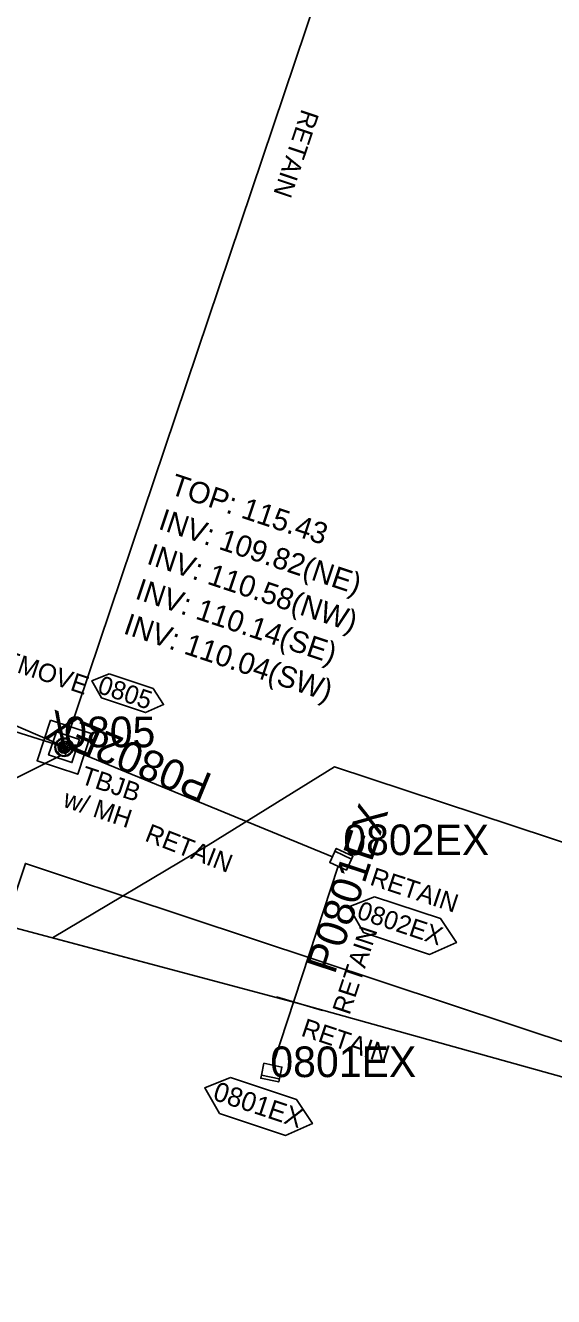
# Model space of a CAD drawing. Extents: x 2296558 to 2299313, y 599200 to 601383.
# Drawn here: x 2299102.6 to 2299188.8, y 599410.6 to 599618.1 of the extents above; entities that cross this region are included whole.
import ezdxf

# ---------------------------------------------------------------- set-up
doc = ezdxf.new("R2010")
doc.units = 0
for name, color, linetype in [('Exist Drainage Structure Catch Basin CELL', 7, 'Continuous'), ('Prop Drainage Structure Box Number Symbol CELL', 7, 'Continuous'), ('Prop Drainage Structure Catch Basin Grate 840 03F Label', 7, 'Continuous'), ('Prop Drainage Structure Catch Basin Grate 840 03G Label', 7, 'Continuous'), ('Prop Drainage Structure Junction Box with Manhole TB CELL', 7, 'Continuous'), ('Prop Drainage Structure Pipe RCP 18in Class IV', 7, 'Continuous'), ('Prop Drainage Structure Pipe Removal', 7, 'Continuous'), ('Prop Drainage Structure Plot Symbol 20 Scale', 7, 'Continuous'), ('Prop Drainage Structure Plot Symbol 50 Scale', 7, 'Continuous'), ('Prop Drainage Structure Retain Label', 7, 'Continuous'), ('Prop Drainage Structure Tops and Inverts LABEL', 7, 'Continuous'), ('Prop Plan Preparation Watershed Post Construction', 7, 'Continuous'), ('Scratch_Level_1', 7, 'Continuous'), ('Scratch_Level_3', 7, 'Continuous'), ('Scratch_Level_5', 7, 'Continuous'), ('Scratch_Level_9', 7, 'Continuous')]:
    doc.layers.add(name, color=color, linetype=linetype)

msp = doc.modelspace()

# ---------------------------------------------------------------- linework, layer by layer
at = {"layer": 'Exist Drainage Structure Catch Basin CELL'}
for p, q in [((2299152.69, 599482.4), (2299152.69, 599482.4)), ((2299154.68, 599483.12), (2299154.68, 599483.12)), ((2299153.63, 599480.86), (2299153.63, 599480.86)), ((2299154.05, 599481.76), (2299154.05, 599481.76)), ((2299155.41, 599481.13), (2299155.41, 599481.13)), ((2299141.31, 599447.72), (2299141.31, 599447.72)), ((2299142.77, 599447.41), (2299142.77, 599447.41)), ((2299142.98, 599448.39), (2299142.98, 599448.39)), ((2299144.24, 599447.1), (2299144.24, 599447.1)), ((2299142.46, 599445.94), (2299142.46, 599445.94))]:
    msp.add_line(p, q, dxfattribs=at)
for points in [[(2299153.11, 599483.3), (2299155.83, 599482.03), (2299156.04, 599482.49), (2299153.32, 599483.76), (2299152.27, 599481.49), (2299154.99, 599480.22), (2299155.83, 599482.03)], [(2299144.03, 599446.12), (2299141.1, 599446.74), (2299141, 599446.25), (2299143.93, 599445.63), (2299144.45, 599448.07), (2299141.51, 599448.7), (2299141.1, 599446.74)]]:
    msp.add_lwpolyline(points, dxfattribs=at)
at = {"layer": 'Prop Drainage Structure Box Number Symbol CELL'}
for points in [[(2299116.25, 599512.25), (2299123.43, 599509.87), (2299125.15, 599507.25), (2299122.23, 599505.96), (2299115.05, 599508.34), (2299113.45, 599511.14), (2299116.25, 599512.25)], [(2299159.58, 599475.89), (2299170.34, 599472.31), (2299172.93, 599468.39), (2299168.55, 599466.45), (2299157.78, 599470.02), (2299155.38, 599474.21), (2299159.58, 599475.89)], [(2299136.08, 599446.35), (2299146.85, 599442.78), (2299149.43, 599438.85), (2299145.05, 599436.91), (2299134.28, 599440.49), (2299131.88, 599444.68), (2299136.08, 599446.35)]]:
    msp.add_lwpolyline(points, dxfattribs=at)
at = {"layer": 'Prop Drainage Structure Junction Box with Manhole TB CELL'}
for p, q in [((2299109.37, 599501.61), (2299109.37, 599501.61)), ((2299107.62, 599500.73), (2299107.62, 599500.73)), ((2299108.49, 599498.98), (2299108.49, 599498.98)), ((2299108.93, 599500.29), (2299108.93, 599500.29)), ((2299110.25, 599499.86), (2299110.25, 599499.86))]:
    msp.add_line(p, q, dxfattribs=at)
for points in [[(2299108.63, 599501.65), (2299108.71, 599501.26), (2299108.75, 599501.27), (2299108.67, 599501.65)], [(2299108.63, 599501.65), (2299108.71, 599501.26), (2299108.75, 599501.27), (2299108.67, 599501.65)], [(2299109.95, 599501.23), (2299109.66, 599500.97), (2299109.68, 599500.94), (2299109.98, 599501.2)], [(2299109.95, 599501.23), (2299109.66, 599500.97), (2299109.68, 599500.94), (2299109.98, 599501.2)], [(2299107.62, 599500.75), (2299108, 599500.63), (2299107.98, 599500.59), (2299107.61, 599500.71)], [(2299107.61, 599500.71), (2299107.98, 599500.59), (2299108, 599500.63), (2299107.62, 599500.75)], [(2299107.91, 599499.36), (2299108.2, 599499.62), (2299108.18, 599499.65), (2299107.88, 599499.39)], [(2299107.91, 599499.36), (2299108.2, 599499.62), (2299108.18, 599499.65), (2299107.88, 599499.39)], [(2299109.23, 599498.94), (2299109.15, 599499.33), (2299109.11, 599499.32), (2299109.19, 599498.93)], [(2299109.23, 599498.94), (2299109.15, 599499.33), (2299109.11, 599499.32), (2299109.19, 599498.93)], [(2299110.25, 599499.88), (2299109.88, 599500), (2299109.86, 599499.96), (2299110.24, 599499.84)], [(2299110.25, 599499.88), (2299109.88, 599500), (2299109.86, 599499.96), (2299110.24, 599499.84)]]:
    msp.add_lwpolyline(points, dxfattribs=at)
for radius in [1.39, 0.99, 0.953, 0.87, 0.625, 0.583, 0.333, 0.292, 0.0834, 0.0416]:
    msp.add_circle((2299108.93, 599500.29), radius, dxfattribs=at)
msp.add_arc((2299108.93, 599500.29), 0.0834, 71.6371, 71.6371, dxfattribs=at)
at = {"layer": 'Prop Drainage Structure Pipe RCP 18in Class IV'}
msp.add_line((2299045.49, 599520.29), (2299107.62, 599500.73), dxfattribs=at)
at = {"layer": 'Prop Drainage Structure Pipe Removal'}
msp.add_line((2299068.84, 599517.73), (2299108.93, 599500.4), dxfattribs=at)
at = {"layer": 'Prop Drainage Structure Plot Symbol 20 Scale'}
msp.add_lwpolyline([(2299107.66, 599502.82), (2299111.46, 599501.56), (2299110.2, 599497.77), (2299106.4, 599499.03)], close=True, dxfattribs=at)
msp.add_circle((2299108.93, 599500.29), 1.5, dxfattribs=at)
at = {"layer": 'Prop Drainage Structure Plot Symbol 50 Scale'}
msp.add_lwpolyline([(2299106.71, 599504.72), (2299113.35, 599502.51), (2299111.15, 599495.87), (2299104.51, 599498.07)], close=True, dxfattribs=at)
msp.add_circle((2299108.93, 599500.29), 1.5, dxfattribs=at)
at = {"layer": 'Prop Plan Preparation Watershed Post Construction'}
msp.add_lwpolyline([(2299299.35, 599416.01), (2299307.79, 599446.97), (2299301.84, 599447.48), (2299293.51, 599450.64), (2299153.01, 599497.07), (2299132.4, 599484.31), (2299107.04, 599469.18), (2299147.02, 599458.5), (2299299.35, 599416.01)], dxfattribs=at)
msp.add_lwpolyline([(2299034.3, 599277.17), (2299068.89, 599265.54), (2299164.35, 599258.21), (2299187.08, 599250.1), (2299278.03, 599200.45), (2299283.1, 599276.07), (2299285.25, 599366.73), (2299299.35, 599416.01), (2299147.02, 599458.5), (2299099.24, 599471.26)], close=True, dxfattribs=at)
at = {"layer": 'Scratch_Level_1'}
msp.add_line((2299143.55, 599459.51), (2299151.1, 599457.31), dxfattribs=at)
msp.add_lwpolyline([(2299299.35, 599416.01), (2299118.35, 599476.09), (2299109.81, 599478.93), (2299102.61, 599481.32), (2299034.3, 599277.17)], dxfattribs=at)
at = {"layer": 'Scratch_Level_9'}
for p, q in [((2299109.37, 599501.61), (2299188.64, 599737.25)), ((2299055.32, 599472.12), (2299108.49, 599498.98)), ((2299152.69, 599482.4), (2299110.25, 599499.86)), ((2299142.98, 599448.39), (2299153.63, 599480.86))]:
    msp.add_line(p, q, dxfattribs=at)

# ---------------------------------------------------------------- texts
at = {"layer": 'Prop Drainage Structure Box Number Symbol CELL'}
for s, height, p in [('0805', 3, (2299114.19, 599509.21)), ('0802EX', 3, (2299156.51, 599472.39)), ('0801EX', 3.15, (2299133.02, 599442.78))]:
    msp.add_text(s, height=height, rotation=341.6372, dxfattribs=at).set_placement(p)
at = {"layer": 'Prop Drainage Structure Catch Basin Grate 840 03F Label'}
for s, p in [('TBJB', (2299111.46, 599494.42)), (' w/ MH', (2299107.51, 599490.99))]:
    msp.add_text(s, height=3, rotation=341.6372, dxfattribs=at).set_placement(p)
at = {"layer": 'Prop Drainage Structure Catch Basin Grate 840 03G Label'}
msp.add_text('REMOVE', height=3, rotation=341.6372, dxfattribs=at).set_placement((2299095.8, 599514.3))
at = {"layer": 'Prop Drainage Structure Retain Label'}
for rotation, p in [(251.38, (2299147.72, 599604.62)), (338.7633, (2299121.93, 599485.07)), (341.6372, (2299158.64, 599477.88)), (71.6794, (2299155.47, 599456.45)), (341.6372, (2299147.43, 599453.22))]:
    msp.add_text('RETAIN', height=3, rotation=rotation, dxfattribs=at).set_placement(p)
at = {"layer": 'Prop Drainage Structure Tops and Inverts LABEL'}
for s, p in [('TOP: 115.43', (2299126.02, 599541.68)), ('INV: 109.82(NE)', (2299124.12, 599535.99)), ('INV: 110.58(NW)', (2299122.23, 599530.3)), ('INV: 110.14(SE)', (2299120.33, 599524.61)), ('INV: 110.04(SW)', (2299118.43, 599518.91))]:
    msp.add_text(s, height=3.5, rotation=341.5664, dxfattribs=at).set_placement(p)
at = {"layer": 'Scratch_Level_3'}
for s, rotation, p in [('P0802EX', 157.638, (2299133.37, 599495.75)), ('P0801EX', 71.8505, (2299153.06, 599463.06))]:
    msp.add_text(s, height=5, rotation=rotation, dxfattribs=at).set_placement(p)
at = {"layer": 'Scratch_Level_5'}
for s, p in [('0805', (2299108.93, 599500.29)), ('0802EX', (2299154.47, 599482.67)), ('0801EX', (2299142.57, 599446.43))]:
    msp.add_text(s, height=5, dxfattribs=at).set_placement(p)

doc.saveas('drawing.dxf')
